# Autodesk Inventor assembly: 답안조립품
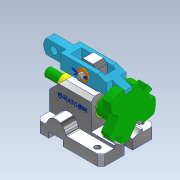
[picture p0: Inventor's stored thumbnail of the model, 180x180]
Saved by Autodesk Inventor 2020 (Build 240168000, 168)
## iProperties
Created: 2022-08
Part Number: 답안조립품
Document SubType Name: Assembly
Designer: user
Author: user
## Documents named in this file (8)
- C:\Users\user\Documents\Inventor\720806V1015\답안조립품.iam
- C:\Users\user\Documents\Inventor\720806V1015\본체.ipt
- C:\Users\user\Documents\Inventor\720806V1015\720806V1015\부시.ipt
- C:\Users\user\Documents\Inventor\720806V1015\720806V1015\분할대.ipt
- C:\Users\user\Documents\Inventor\720806V1015\720806V1015\분할축.ipt
- C:\Users\user\Documents\Inventor\720806V1015\720806V1015\분할핀.ipt
- C:\Users\user\Documents\Inventor\720806V1015\720806V1015\와셔.ipt
- C:\Users\user\Documents\Inventor\720806V1015\720806V1015\클레비스핀.ipt
